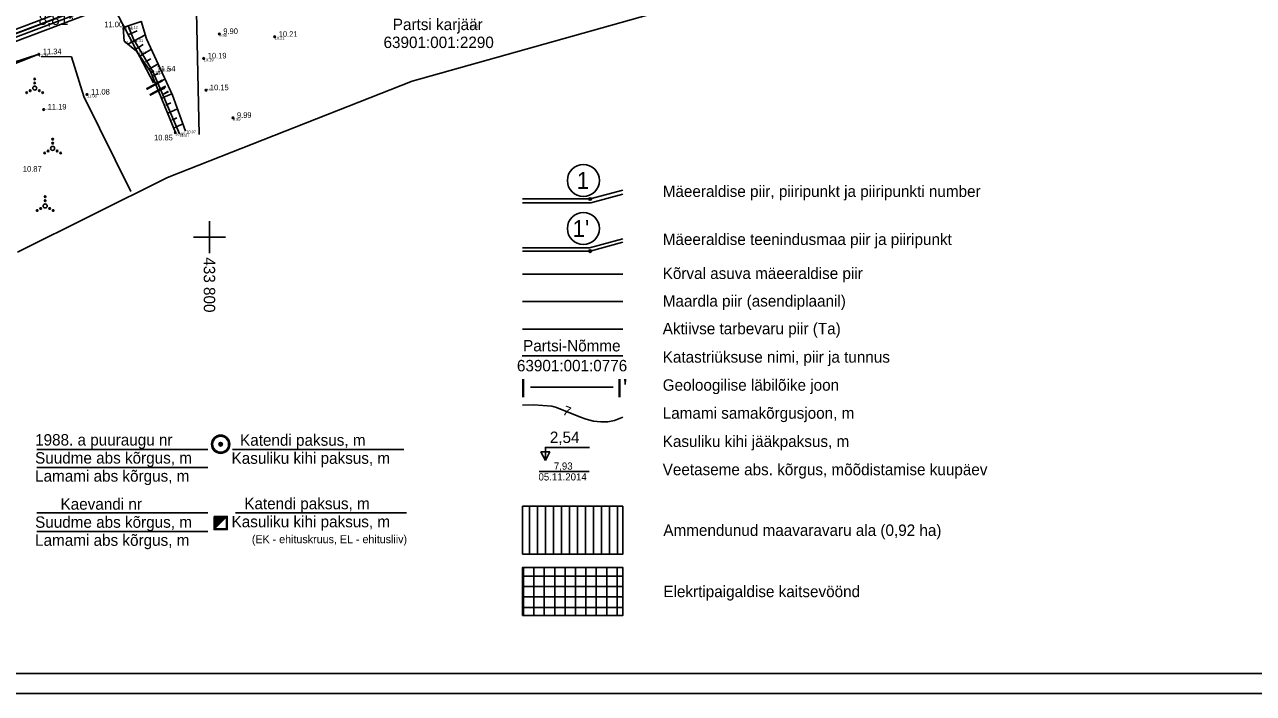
# Model space of a CAD drawing. Extents: x 433497 to 434382, y 6534486 to 6534993.
# Drawn here: x 433753.8 to 434060.9, y 6534486 to 6534653.1 of the extents above; entities that cross this region are included whole.
import ezdxf

# ---------------------------------------------------------------- set-up
doc = ezdxf.new("R2010")
doc.units = 0
for name, color, linetype in [('Default', 7, 'Continuous'), ('GEOLPUNKT', 7, 'Continuous'), ('HALJASTUS', 7, 'Continuous'), ('jääkpaksus', 7, 'Continuous'), ('Kaitsevöönd', 7, 'Continuous'), ('kataster', 7, 'Continuous'), ('KORGUS-EH2000', 7, 'Continuous'), ('l__x00e4__bil__x00f5__iked', 7, 'Continuous'), ('Level 21', 7, 'Continuous'), ('MOOTKORG-EH2000', 7, 'Continuous'), ('PIIR', 7, 'Continuous'), ('RELJEEF', 7, 'Continuous'), ('Täide', 7, 'Continuous'), ('VORK', 7, 'Continuous'), ('VORMISTUS', 7, 'Continuous')]:
    doc.layers.add(name, color=color, linetype=linetype)

msp = doc.modelspace()

# ---------------------------------------------------------------- linework, layer by layer
at = {"layer": 'Default'}
msp.add_lwpolyline([(433617.12, 6534791.02), (433632.75, 6534606.04), (434137.38, 6534796.52), (434127.69, 6534855.6), (433968.21, 6534911.92), (433942.38, 6534904.03), (433920.99, 6534907.27)], close=True, dxfattribs=at)
msp.add_lwpolyline([(433617.12, 6534791.02), (433632.75, 6534606.04), (434137.38, 6534796.52), (434127.69, 6534855.6), (433968.21, 6534911.92), (433942.38, 6534904.03), (433920.99, 6534907.27)], close=True, dxfattribs=at)
msp.add_lwpolyline([(433617.12, 6534791.02), (433632.75, 6534606.04), (434137.38, 6534796.52), (434127.69, 6534855.6), (433968.21, 6534911.92), (433942.38, 6534904.03), (433920.99, 6534907.27)], close=True, dxfattribs=at)
at = {"layer": 'HALJASTUS'}
msp.add_lwpolyline([(433780.36, 6534611.34), (433768.59, 6534635.12), (433765.53, 6534645.01), (433757.92, 6534645.1)], dxfattribs=at)
for centre, radius in [((433756.35, 6534639.5), 0.2), ((433754.35, 6534636.05), 0.2), ((433755.22, 6534636.55), 0.2), ((433756.35, 6534637.2), 0.5), ((433756.35, 6534638.5), 0.2), ((433757.48, 6534636.55), 0.2), ((433758.35, 6534636.05), 0.2), ((433760.82, 6534624.45), 0.2), ((433760.82, 6534623.45), 0.2), ((433758.82, 6534621), 0.2), ((433759.69, 6534621.5), 0.2), ((433760.82, 6534622.15), 0.5), ((433761.95, 6534621.5), 0.2), ((433762.82, 6534621), 0.2), ((433758.95, 6534607.78), 0.5), ((433758.95, 6534610.08), 0.2), ((433758.95, 6534609.08), 0.2), ((433756.95, 6534606.63), 0.2), ((433757.82, 6534607.13), 0.2), ((433760.08, 6534607.13), 0.2), ((433760.95, 6534606.63), 0.2)]:
    msp.add_circle(centre, radius, dxfattribs=at)
at = {"layer": 'jääkpaksus'}
msp.add_lwpolyline([(433883.93, 6534544.16), (433883.93, 6534547.46), (433894.93, 6534547.46)], dxfattribs=at)
msp.add_lwpolyline([(433883.93, 6534544.16), (433882.83, 6534546.36), (433885.03, 6534546.36)], close=True, dxfattribs=at)
at = {"layer": 'Kaitsevöönd'}
for p, q in [((433878.47, 6534505.49), (433878.47, 6534517.49)), ((433881.07, 6534505.49), (433881.07, 6534517.49)), ((433883.67, 6534505.49), (433883.67, 6534517.49)), ((433886.27, 6534505.49), (433886.27, 6534517.49)), ((433888.87, 6534505.49), (433888.87, 6534517.49)), ((433891.47, 6534505.49), (433891.47, 6534517.49)), ((433894.07, 6534505.49), (433894.07, 6534517.49)), ((433896.67, 6534505.49), (433896.67, 6534517.49)), ((433899.27, 6534505.49), (433899.27, 6534517.49)), ((433901.87, 6534505.49), (433901.87, 6534517.49)), ((433878.26, 6534515.32), (433903.26, 6534515.32)), ((433878.26, 6534512.72), (433903.26, 6534512.72)), ((433878.26, 6534510.12), (433903.26, 6534510.12)), ((433878.26, 6534507.52), (433903.26, 6534507.52))]:
    msp.add_line(p, q, dxfattribs=at)
msp.add_lwpolyline([(433878.26, 6534505.49), (433903.26, 6534505.49), (433903.26, 6534517.49), (433878.26, 6534517.49)], close=True, dxfattribs=at)
at = {"layer": 'kataster'}
msp.add_lwpolyline([(433617.1, 6534791), (433632.77, 6534606.03), (434137.45, 6534796.47), (434127.83, 6534855.59), (433950.03, 6534918.39)], close=True, dxfattribs=at)
at = {"layer": 'KORGUS-EH2000'}
for centre in [(433802.47, 6534650.71), (433816.32, 6534650.02), (433757.36, 6534645.66), (433798.58, 6534644.61), (433785.83, 6534641.36), (433769.41, 6534635.6), (433799.12, 6534636.68), (433758.6, 6534631.85), (433805.87, 6534629.77), (433791.49, 6534626.08)]:
    msp.add_circle(centre, 0.2, dxfattribs=at)
at = {"layer": 'l__x00e4__bil__x00f5__iked'}
msp.add_lwpolyline([(433633.89, 6534824.09), (433654.74, 6534802.08), (433736.83, 6534712.71), (433742.79, 6534710.72), (433773.91, 6534661.57), (433785.99, 6534638.56)], dxfattribs=at)
at = {"layer": 'Level 21'}
msp.add_line((433878.26, 6534583.87), (433903.26, 6534583.87), dxfattribs=at)
at = {"layer": 'PIIR'}
msp.add_line((433796.55, 6534667.85), (433797.42, 6534625.62), dxfattribs=at)
for points in [[(433632.02, 6534604.84), (434138.25, 6534795.94), (434128.47, 6534856.13), (433968.23, 6534912.82), (433942.33, 6534904.85), (433920.95, 6534908.16), (433616.33, 6534791.52), (433632.02, 6534604.84)], [(433632.73, 6534605.96), (434137.35, 6534796.45), (434127.75, 6534855.54), (433968.21, 6534911.98), (433942.39, 6534904.03), (433921.04, 6534907.34), (433617.17, 6534790.99), (433632.73, 6534605.96)], [(433633.45, 6534604.3), (434134.89, 6534793.6)]]:
    msp.add_lwpolyline(points, dxfattribs=at)
msp.add_lwpolyline([(433618.23, 6534790.33), (433921.15, 6534906.31), (433942.46, 6534903.01), (433968.19, 6534910.92), (434126.86, 6534854.79), (434136.24, 6534797.1), (433633.62, 6534607.36)], close=True, dxfattribs=at)
at = {"layer": 'RELJEEF'}
for p, q in [((433779.69, 6534652.74), (433778.46, 6534652.33)), ((433779.69, 6534652.74), (433782.97, 6534653.83)), ((433781.95, 6534651.52), (433780.41, 6534650.88)), ((433779.51, 6534650.5), (433780.41, 6534650.88)), ((433781.22, 6534649.05), (433779.6, 6534648.21)), ((433781.22, 6534649.05), (433784.01, 6534650.5)), ((433783.45, 6534648.06), (433782.25, 6534647.34)), ((433755.99, 6534645.22), (433756.01, 6534645.13)), ((433757.36, 6534645.66), (433757.36, 6534645.66)), ((433757.36, 6534645.66), (433757.36, 6534645.66)), ((433781.79, 6534647.06), (433782.25, 6534647.34)), ((433783.28, 6534645.62), (433782.61, 6534645.22)), ((433783.28, 6534645.62), (433785.49, 6534646.95)), ((433754.11, 6534644.5), (433754.08, 6534644.6)), ((433784.02, 6534643.74), (433784.31, 6534643.91)), ((433785.32, 6534644.52), (433784.31, 6534643.91)), ((433785.34, 6534642.19), (433784.86, 6534641.93)), ((433785.34, 6534642.19), (433787.21, 6534643.23)), ((433785.99, 6534640.3), (433786.25, 6534640.42)), ((433787.17, 6534640.85), (433786.25, 6534640.42)), ((433787.04, 6534638.58), (433788.97, 6534639.41)), ((433787.04, 6534638.58), (433786.49, 6534638.34)), ((433787.54, 6534636.62), (433787.83, 6534636.74)), ((433788.82, 6534637.17), (433787.83, 6534636.74)), ((433788.62, 6534634.91), (433790.64, 6534635.78)), ((433788.62, 6534634.91), (433788, 6534634.64)), ((433789.08, 6534632.93), (433789.41, 6534633.07)), ((433790.38, 6534633.49), (433789.41, 6534633.07)), ((433790.21, 6534631.23), (433789.51, 6534630.93)), ((433790.21, 6534631.23), (433792.03, 6534632.02)), ((433791.86, 6534629.77), (433791, 6534629.4)), ((433790.63, 6534629.24), (433791, 6534629.4)), ((433791.79, 6534627.56), (433791.02, 6534627.23)), ((433791.79, 6534627.56), (433793.39, 6534628.25))]:
    msp.add_line(p, q, dxfattribs=at)
for points in [[(433778.45, 6534652.38), (433778.69, 6534648.96), (433781.8, 6534646.4), (433785.28, 6534641.31), (433791.48, 6534626.08)], [(433779.69, 6534652.74), (433779.83, 6534652.32), (433781, 6534649.42), (433785.83, 6534641.36), (433792.55, 6534625.81)], [(433779.69, 6534652.74), (433779.83, 6534652.32), (433781, 6534649.42), (433785.84, 6534641.37), (433792.55, 6534625.81)], [(433794.04, 6534626.46), (433790.8, 6534635.44), (433784.31, 6534649.52), (433782.94, 6534653.93)], [(433659.05, 6534607.94), (433662.6, 6534610.35), (433674.02, 6534614.44), (433690.03, 6534620.09), (433707.72, 6534627.15), (433725.77, 6534634.12), (433743.96, 6534641.35), (433757.36, 6534645.66)], [(433659.05, 6534607.94), (433659.05, 6534607.94), (433663.03, 6534609.44), (433674.03, 6534613.43), (433690.5, 6534619.59), (433707.69, 6534626.56), (433726.1, 6534633.69), (433744.05, 6534640.46), (433757.36, 6534645.66)]]:
    msp.add_lwpolyline(points, dxfattribs=at)
at = {"layer": 'Täide'}
for p, q in [((433879.99, 6534520.79), (433879.99, 6534532.79)), ((433881.99, 6534520.79), (433881.99, 6534532.79)), ((433883.99, 6534520.79), (433883.99, 6534532.79)), ((433885.99, 6534520.79), (433885.99, 6534532.79)), ((433887.99, 6534520.79), (433887.99, 6534532.79)), ((433889.99, 6534520.79), (433889.99, 6534532.79)), ((433891.99, 6534520.79), (433891.99, 6534532.79)), ((433893.99, 6534520.79), (433893.99, 6534532.79)), ((433895.99, 6534520.79), (433895.99, 6534532.79)), ((433897.99, 6534520.79), (433897.99, 6534532.79)), ((433899.99, 6534520.79), (433899.99, 6534532.79)), ((433901.99, 6534520.79), (433901.99, 6534532.79))]:
    msp.add_line(p, q, dxfattribs=at)
at = {"layer": 'VORK'}
for p, q in [((433800, 6534604), (433800, 6534596)), ((433796, 6534600), (433804, 6534600))]:
    msp.add_line(p, q, dxfattribs=at)
at = {"layer": 'VORMISTUS'}
for p, q in [((433878.26, 6534590.77), (433903.26, 6534590.77)), ((433878.26, 6534576.97), (433903.26, 6534576.97)), ((433878.15, 6534570.37), (433903.26, 6534570.37)), ((433880.22, 6534562.52), (433900.86, 6534562.52)), ((433756.85, 6534546.97), (433799.63, 6534546.97)), ((433805.79, 6534546.97), (433848.57, 6534546.97)), ((433756.85, 6534542.43), (433799.63, 6534542.43)), ((433882.37, 6534541.42), (433894.9, 6534541.42)), ((433756.85, 6534531.16), (433799.63, 6534531.16)), ((433801.3, 6534527.1), (433804.3, 6534530.1)), ((433801.3, 6534527.13), (433804.27, 6534530.1)), ((433801.3, 6534527.2), (433804.2, 6534530.1)), ((433801.3, 6534527.27), (433804.13, 6534530.1)), ((433801.3, 6534527.34), (433804.05, 6534530.1)), ((433801.3, 6534527.41), (433803.98, 6534530.1)), ((433801.3, 6534527.48), (433803.91, 6534530.1)), ((433801.3, 6534527.55), (433803.84, 6534530.1)), ((433801.3, 6534527.62), (433803.77, 6534530.1)), ((433801.3, 6534527.7), (433803.7, 6534530.1)), ((433801.3, 6534527.77), (433803.63, 6534530.1)), ((433801.3, 6534527.84), (433803.56, 6534530.1)), ((433801.3, 6534527.91), (433803.49, 6534530.1)), ((433801.3, 6534527.98), (433803.42, 6534530.1)), ((433801.3, 6534528.05), (433803.35, 6534530.1)), ((433801.3, 6534528.12), (433803.28, 6534530.1)), ((433801.3, 6534528.19), (433803.21, 6534530.1)), ((433801.3, 6534528.26), (433803.14, 6534530.1)), ((433801.3, 6534528.33), (433803.06, 6534530.1)), ((433801.3, 6534528.4), (433802.99, 6534530.1)), ((433801.3, 6534528.47), (433802.92, 6534530.1)), ((433801.3, 6534528.54), (433802.85, 6534530.1)), ((433801.3, 6534528.61), (433802.78, 6534530.1)), ((433801.3, 6534528.69), (433802.71, 6534530.1)), ((433801.3, 6534528.76), (433802.64, 6534530.1)), ((433801.3, 6534528.83), (433802.57, 6534530.1)), ((433801.3, 6534528.9), (433802.5, 6534530.1)), ((433801.3, 6534528.97), (433802.43, 6534530.1)), ((433801.3, 6534529.04), (433802.36, 6534530.1)), ((433801.3, 6534529.11), (433802.29, 6534530.1)), ((433801.3, 6534529.18), (433802.22, 6534530.1)), ((433801.3, 6534529.25), (433802.15, 6534530.1)), ((433801.3, 6534529.32), (433802.07, 6534530.1)), ((433801.3, 6534529.39), (433802, 6534530.1)), ((433801.3, 6534529.46), (433801.93, 6534530.1)), ((433801.3, 6534529.53), (433801.86, 6534530.1)), ((433801.3, 6534529.6), (433801.79, 6534530.1)), ((433801.3, 6534529.68), (433801.72, 6534530.1)), ((433801.3, 6534529.75), (433801.65, 6534530.1)), ((433801.3, 6534529.82), (433801.58, 6534530.1)), ((433801.3, 6534529.89), (433801.51, 6534530.1)), ((433801.3, 6534529.96), (433801.44, 6534530.1)), ((433801.3, 6534530.03), (433801.37, 6534530.1)), ((433806.49, 6534531.13), (433849.27, 6534531.13)), ((433756.85, 6534526.43), (433799.63, 6534526.43))]:
    msp.add_line(p, q, dxfattribs=at)
for points in [[(433496.62, 6534983.07), (433496.62, 6534486.03), (434381.62, 6534486.03), (434381.62, 6534983.07)], [(434376.62, 6534978.07), (433516.62, 6534978.07), (433516.62, 6534491.03), (434376.62, 6534491.03)], [(433878.26, 6534520.79), (433903.26, 6534520.79), (433903.26, 6534532.79), (433878.26, 6534532.79)], [(433801.16, 6534530.24), (433804.44, 6534530.24), (433804.44, 6534526.96), (433801.16, 6534526.96)], [(433801.3, 6534530.1), (433804.3, 6534530.1), (433804.3, 6534527.1), (433801.3, 6534527.1)]]:
    msp.add_lwpolyline(points, close=True, dxfattribs=at)
for points in [[(433752.08, 6534596.22), (433789.5, 6534614.84), (433850.68, 6534638.91), (433933.41, 6534662.28), (434004.05, 6534676.58), (434088.7, 6534717.82)], [(433752.08, 6534596.22), (433789.5, 6534614.84), (433850.68, 6534638.91), (433933.41, 6534662.28), (434004.05, 6534676.58), (434088.7, 6534717.82)], [(433903.26, 6534611.69), (433895.12, 6534609.51), (433878.19, 6534609.51)], [(433903.26, 6534610.69), (433895.29, 6534608.51), (433878.19, 6534608.51)], [(433903.26, 6534599.53), (433894.94, 6534597.35), (433878.19, 6534597.35)], [(433903.26, 6534598.69), (433895.12, 6534596.51), (433878.19, 6534596.51)], [(433878.19, 6534557.99), (433881.06, 6534558.12), (433885.55, 6534557.73), (433886.7, 6534557.44)], [(433886.7, 6534557.44), (433892.75, 6534554.99), (433894.13, 6534554.51), (433895.93, 6534554.06), (433897.76, 6534553.84), (433899.56, 6534553.88), (433901.25, 6534554.18), (433903.26, 6534554.99)]]:
    msp.add_lwpolyline(points, dxfattribs=at)
for centre, radius in [((433893.43, 6534614.14), 4), ((433895.12, 6534609.51), 0.325), ((433893.43, 6534602.14), 4), ((433895.12, 6534596.51), 0.325), ((433802.8, 6534548.26), 2.28), ((433802.8, 6534548.26), 2), ((433802.8, 6534548.26), 0.45), ((433802.8, 6534548.26), 0.4), ((433802.8, 6534548.26), 0.35), ((433802.8, 6534548.26), 0.3), ((433802.8, 6534548.26), 0.25), ((433802.8, 6534548.26), 0.2), ((433802.8, 6534548.26), 0.15), ((433802.8, 6534548.26), 0.1), ((433802.8, 6534548.26), 0.05)]:
    msp.add_circle(centre, radius, dxfattribs=at)

# ---------------------------------------------------------------- texts
at = {"layer": 'GEOLPUNKT'}
msp.add_text('8,81*', height=2.85, dxfattribs=at).set_placement((433757.31, 6534653))
at = {"layer": 'jääkpaksus'}
msp.add_text(' 2,54', height=2.85, rotation=360, dxfattribs=at).set_placement((433883.99, 6534548.57))
at = {"layer": 'kataster'}
for s, p in [('Partsi karjäär', (433845.82, 6534651.69)), ('63901:001:2290', (433843.5, 6534647.21)), ('Partsi-Nõmme', (433878.37, 6534571.45)), ('63901:001:0776', (433876.83, 6534566.47))]:
    msp.add_text(s, height=2.85, dxfattribs=at).set_placement(p)
at = {"layer": 'KORGUS-EH2000'}
for s, p in [('11.00', (433773.74, 6534652.41)), ('9.90', (433803.47, 6534650.71)), ('10.21', (433817.32, 6534650.02)), ('11.34', (433758.36, 6534645.66)), ('10.19', (433799.58, 6534644.61)), ('11.54', (433786.83, 6534641.36)), ('11.08', (433770.41, 6534635.6)), ('10.15', (433800.12, 6534636.68)), ('11.19', (433759.6, 6534631.85)), ('9.99', (433806.87, 6534629.77)), ('10.85', (433786.16, 6534624.14)), ('10.87', (433753.39, 6534616.32))]:
    msp.add_text(s, height=1.4, dxfattribs=at).set_placement(p)
at = {"layer": 'l__x00e4__bil__x00f5__iked'}
msp.add_text("II'", height=4.58, rotation=298.6589, dxfattribs=at).set_placement((433783.85, 6534637.69))
for s, p in [('I', (433877.55, 6534559.97)), ("I'", (433901.59, 6534559.97))]:
    msp.add_text(s, height=4.58, dxfattribs=at).set_placement(p)
at = {"layer": 'MOOTKORG-EH2000'}
for s, height, p in [('11.06', 0.7, (433778.45, 6534651.68)), ('11.12', 0.7, (433779.69, 6534652.04)), ('9.98', 0.7, (433865.17, 6534652.32)), ('11.26', 0.7, (433778.7, 6534648.26)), ('12.31', 0.7, (433781, 6534648.72)), ('9.90', 0.7, (433802.47, 6534650.01)), ('10.21', 0.7, (433816.32, 6534649.32)), ('11.34', 0.7, (433757.36, 6534644.96)), ('11.34', 0.7, (433757.36, 6534644.96)), ('11.14', 0.7, (433781.81, 6534645.7)), ('10.14', 0.7, (433787.86, 6534641.36)), ('10.19', 0.7, (433798.58, 6534643.91)), ('11.13', 0.7, (433785.28, 6534640.61)), ('11.54', 0.7, (433785.83, 6534640.66)), ('10.15', 0.35, (433799.12, 6534636.68)), ('11.08', 0.7, (433769.41, 6534634.9)), ('11.19', 0.35, (433758.6, 6534631.85)), ('9.99', 0.7, (433805.87, 6534629.07)), ('10.07', 0.7, (433794.21, 6534625.93)), ('10.85', 0.7, (433791.49, 6534625.38)), ('11.27', 0.7, (433792.55, 6534625.11))]:
    msp.add_text(s, height=height, dxfattribs=at).set_placement(p)
at = {"layer": 'VORK'}
msp.add_text(' 433 800', height=2.85, rotation=270, dxfattribs=at).set_placement((433798.58, 6534596))
at = {"layer": 'VORMISTUS'}
for s, height, p in [('1', 4.2, (433891.76, 6534612.04)), ('Mäeeraldise piir, piiripunkt ja piiripunkti number', 2.85, (433913.26, 6534610.02)), ("1'", 4.2, (433890.71, 6534600.04)), ('Mäeeraldise teenindusmaa piir ja piiripunkt', 2.85, (433913.26, 6534598.02)), ('Kõrval asuva mäeeraldise piir', 2.85, (433913.26, 6534589.53)), ('Maardla piir (asendiplaanil)', 2.85, (433913.26, 6534582.63)), ('Aktiivse tarbevaru piir (Ta)', 2.85, (433913.26, 6534575.73)), ('Katastriüksuse nimi, piir ja tunnus', 2.85, (433913.26, 6534568.63)), ('Geoloogilise läbilõike joon', 2.85, (433913.26, 6534561.63)), ('Lamami samakõrgusjoon, m', 2.85, (433913.26, 6534554.63)), ('1988. a puuraugu nr', 2.85, (433756.44, 6534547.94)), ('  Katendi paksus, m', 2.85, (433805.53, 6534547.88)), ('Kasuliku kihi jääkpaksus, m', 2.85, (433913.26, 6534547.58)), ('Suudme abs kõrgus, m', 2.85, (433756.44, 6534543.43)), ('Kasuliku kihi paksus, m', 2.85, (433805.53, 6534543.37)), ('7,93', 1.8, (433886.06, 6534541.91)), ('Lamami abs kõrgus, m', 2.85, (433756.44, 6534538.91)), ('05.11.2014', 1.8, (433882.22, 6534539.21)), ('Veetaseme abs. kõrgus, mõõdistamise kuupäev', 2.85, (433913.26, 6534540.53)), ('      Kaevandi nr', 2.85, (433756.44, 6534531.91)), ('   Katendi paksus, m', 2.85, (433805.53, 6534532.03)), ('Suudme abs kõrgus, m', 2.85, (433756.44, 6534527.4)), ('Kasuliku kihi paksus, m', 2.85, (433805.53, 6534527.52)), ('Ammendunud maavaravaru ala (0,92 ha)', 2.85, (433913.42, 6534525.37)), ('Lamami abs kõrgus, m', 2.85, (433756.44, 6534522.89)), ('(EK - ehituskruus, EL - ehitusliiv)', 2, (433810.59, 6534523.55)), ('Elekrtipaigaldise kaitsevöönd', 2.85, (433913.42, 6534510.07))]:
    msp.add_text(s, height=height, dxfattribs=at).set_placement(p)
msp.add_text('7', height=2.4, rotation=338.468, dxfattribs=at).set_placement((433888.06, 6534555.76))

doc.saveas('drawing.dxf')
